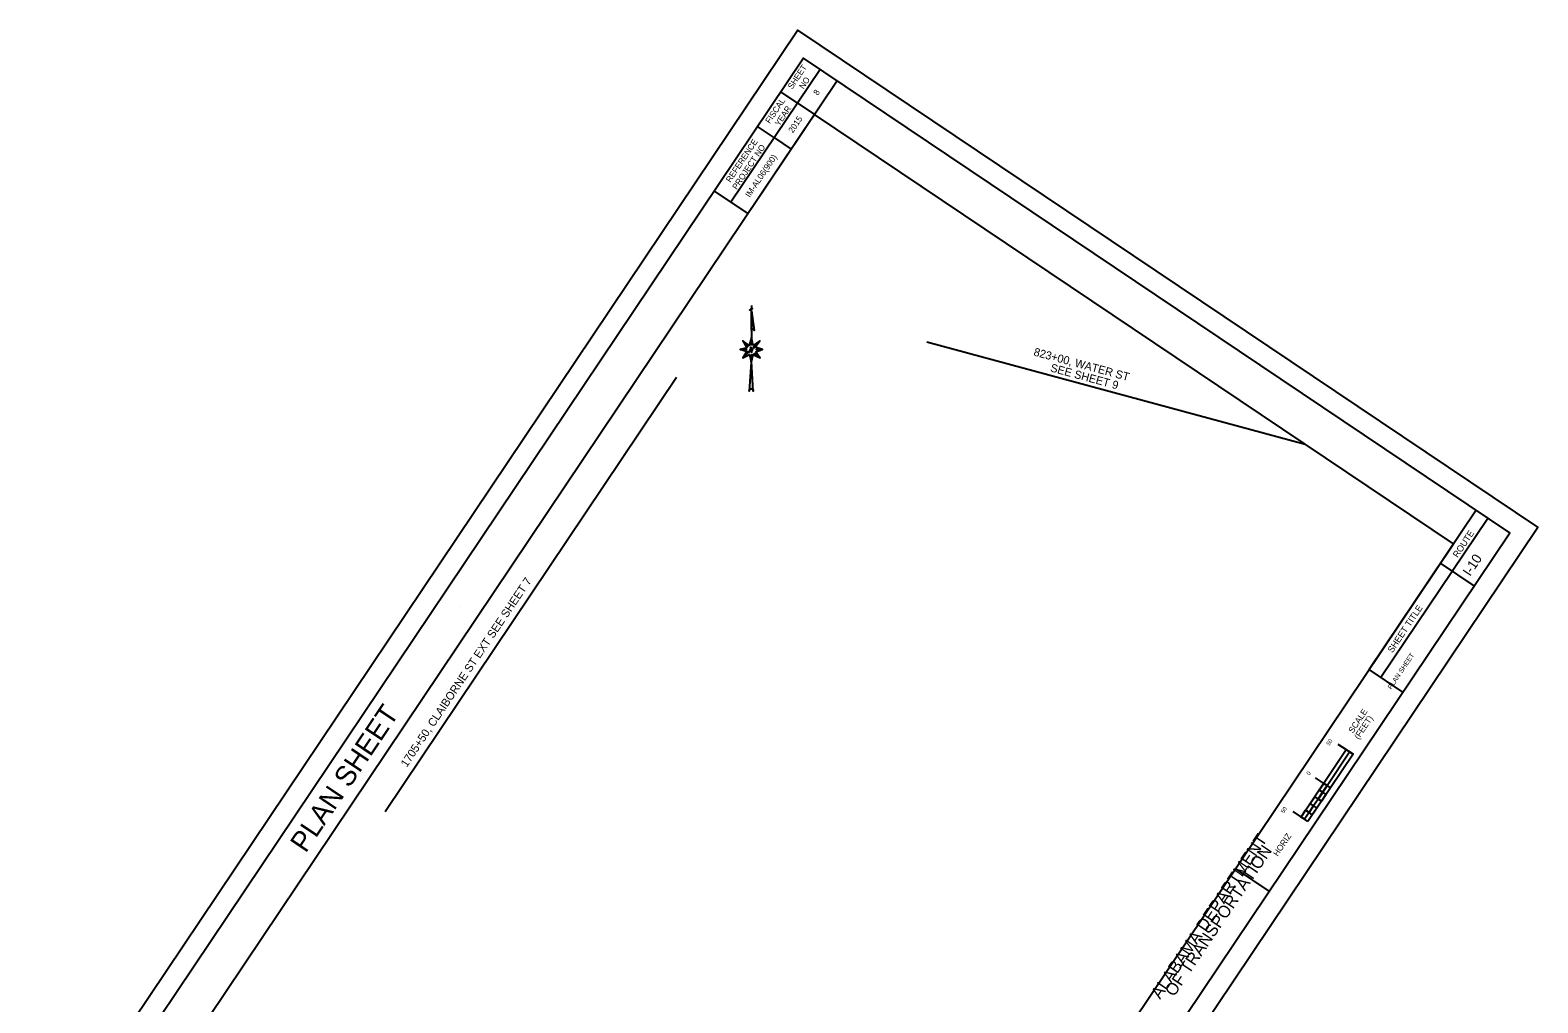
# Model space of a CAD drawing. Extents: x 1797784 to 1799645, y 248583 to 250607.
# Drawn here: x 1797784 to 1799645, y 249407 to 250607 of the extents above; entities that cross this region are included whole.
import ezdxf

# ---------------------------------------------------------------- set-up
doc = ezdxf.new("R2010")
doc.units = 0
for name, color, linetype in [('29', 7, 'Continuous'), ('ANNO-SHT', 7, 'Continuous'), ('ANNO-SYMB', 7, 'Continuous'), ('ANNO-TXT', 7, 'Continuous'), ('DRAINAGE', 7, 'Continuous'), ('Level 1', 7, 'Continuous'), ('Level 57', 7, 'Continuous'), ('Level 6', 7, 'Continuous'), ('Level 62', 7, 'Continuous'), ('SHT-BDR', 7, 'Continuous'), ('SHT-BNDRY', 7, 'Continuous')]:
    doc.layers.add(name, color=color, linetype=linetype)

# ---------------------------------------------------------------- blocks, each defined once
blk = doc.blocks.new('SC47208')
at = {"layer": 'Level 1'}
blk.add_line((0, 0), (0, 0), dxfattribs=at)

msp = doc.modelspace()

# ---------------------------------------------------------------- linework, layer by layer
at = {"layer": '29'}
msp.add_line((1798222.5, 249643.4), (1798582.1, 250179), dxfattribs=at)
msp.add_lwpolyline([(1798891.2, 250222.5), (1799358.1, 250096.4)], dxfattribs=at)
at = {"layer": 'ANNO-SYMB'}
for p, q in [((1799408.9, 249719.5), (1799353.1, 249636.4)), ((1799417.2, 249713.9), (1799361.4, 249630.9)), ((1799417.2, 249713.9), (1799398.9, 249726.1)), ((1799417.2, 249713.9), (1799413, 249716.7)), ((1799417.2, 249713.9), (1799413, 249716.7)), ((1799417.2, 249713.9), (1799413, 249716.7)), ((1799389.3, 249672.4), (1799371, 249684.6)), ((1799389.3, 249672.4), (1799371, 249684.6)), ((1799389.3, 249672.4), (1799371, 249684.6)), ((1799385.2, 249675.2), (1799374, 249658.6)), ((1799385.2, 249675.2), (1799381, 249677.9)), ((1799385.2, 249675.2), (1799381, 249677.9)), ((1799385.2, 249675.2), (1799381, 249677.9)), ((1799361.4, 249630.9), (1799343.2, 249643.1)), ((1799362.9, 249641.9), (1799358.7, 249644.7)), ((1799362.9, 249641.9), (1799358.7, 249644.7))]:
    msp.add_line(p, q, dxfattribs=at)
for points in [[(1799385.2, 249675.2), (1799413, 249716.7), (1799417.2, 249713.9), (1799389.3, 249672.4)], [(1799375.4, 249669.6), (1799381, 249677.9), (1799385.2, 249675.2), (1799379.6, 249666.9)], [(1799364.3, 249653), (1799369.9, 249661.3), (1799374, 249658.6), (1799368.4, 249650.3)], [(1799374, 249658.6), (1799379.6, 249666.9), (1799383.7, 249664.1), (1799378.2, 249655.8)], [(1799353.1, 249636.4), (1799358.7, 249644.7), (1799362.9, 249641.9), (1799357.3, 249633.6)], [(1799362.9, 249641.9), (1799368.4, 249650.3), (1799372.6, 249647.5), (1799367, 249639.2)]]:
    msp.add_lwpolyline(points, close=True, dxfattribs=at)
at = {"layer": 'ANNO-TXT'}
for p, q in [((1799539.4, 249939.7), (1799583.5, 250005.3)), ((1799451.6, 249808.8), (1799539.4, 249939.7))]:
    msp.add_line(p, q, dxfattribs=at)
at = {"layer": 'Level 57'}
msp.add_line((1798674.7, 250267.3), (1798674.6, 250264.8), dxfattribs=at)
for points in [[(1798675.8, 250263.7), (1798675.7, 250263.7), (1798675.8, 250263.5), (1798675.9, 250263.7), (1798675.8, 250263.9), (1798675.6, 250263.8), (1798675.3, 250263.7), (1798675.2, 250263.6), (1798675, 250263.2), (1798674.9, 250262.8), (1798674.7, 250262.2), (1798674.6, 250262.1), (1798674.5, 250261.7), (1798674.5, 250262.3), (1798674.4, 250263.2), (1798674.2, 250263.8), (1798674.3, 250263.2), (1798674.5, 250261.7), (1798674.4, 250263.2), (1798674.2, 250263.8), (1798674.1, 250263.3), (1798673.7, 250262.2), (1798673.4, 250261.7), (1798673.2, 250261.6), (1798672.9, 250261.6), (1798672.8, 250261.7), (1798672.8, 250261.9), (1798672.9, 250262), (1798673, 250261.9), (1798673, 250261.8)], [(1798674.6, 250260.8), (1798678.2, 250236.6), (1798678.1, 250237.4), (1798677.9, 250237.7), (1798677.5, 250238), (1798677, 250238.3), (1798676.7, 250238.3), (1798676.3, 250238.3), (1798675.9, 250238.4), (1798675.6, 250238.2), (1798675.3, 250238.1), (1798674.9, 250237.8), (1798674.8, 250237.6), (1798674.6, 250237.3), (1798674.6, 250237.1), (1798674.6, 250260.6), (1798674.7, 250227.7)], [(1798674.6, 250227.7), (1798674.5, 250218.8), (1798674.6, 250227.8), (1798671.9, 250218.2), (1798664.1, 250223.7), (1798670.2, 250217), (1798664.1, 250223.7), (1798669, 250215.2), (1798661, 250213.2), (1798668.6, 250213), (1798661.1, 250213.4), (1798668.9, 250210.6), (1798664.3, 250202.7), (1798670, 250208.5), (1798664.3, 250202.7), (1798672.2, 250207.1), (1798674.5, 250198.2), (1798674.4, 250206.5), (1798674.5, 250198), (1798676.5, 250207), (1798685.4, 250202.8), (1798676.4, 250207), (1798674.5, 250197.7), (1798672.1, 250161.7), (1798672.3, 250162.9), (1798672.7, 250163.7), (1798673.1, 250164.2), (1798673.8, 250164.6), (1798674.3, 250164.7), (1798674.9, 250164.7), (1798675.4, 250164.5), (1798676, 250164.2), (1798676.4, 250163.7), (1798676.7, 250163.1), (1798676.9, 250162.6), (1798677, 250161.7), (1798674.6, 250198.2), (1798676.4, 250207.1), (1798685.3, 250202.8), (1798678.5, 250208.1), (1798685.2, 250203), (1798680, 250210.1), (1798688, 250213.1), (1798680.4, 250213), (1798688.2, 250213.1), (1798679.4, 250215.9), (1798684.9, 250223.7), (1798678.5, 250217.4), (1798684.9, 250223.7), (1798677, 250218.2), (1798674.7, 250227.6)], [(1798678.5, 250215.7), (1798678.3, 250215.5), (1798678.6, 250215.2), (1798678.7, 250215.6), (1798678.6, 250215.9), (1798678.5, 250216.1), (1798677.9, 250216), (1798677.3, 250215.7), (1798676.3, 250214.5), (1798676.1, 250214), (1798675.8, 250212.8), (1798675.3, 250211.6), (1798674.8, 250210.7), (1798674.7, 250209.3), (1798674.7, 250211.1), (1798674.5, 250213.3), (1798674.4, 250214.5), (1798673.9, 250215.9), (1798673.9, 250214.2), (1798674.1, 250212), (1798674.4, 250210.5), (1798674.7, 250209.4), (1798674.6, 250211.4), (1798674.4, 250214.5), (1798673.9, 250216), (1798673.6, 250214.5), (1798672.9, 250212.9), (1798672.6, 250212.2), (1798672.4, 250211.4), (1798672, 250210.6), (1798671.7, 250210.1), (1798671.4, 250209.5), (1798670.6, 250209.2), (1798670, 250209.3), (1798669.7, 250209.6), (1798669.7, 250210.3), (1798670.1, 250210.6), (1798670.4, 250210.2), (1798670.1, 250210)]]:
    msp.add_lwpolyline(points, dxfattribs=at)
at = {"layer": 'Level 6'}
for p, q in [((1798759.4, 250558.6), (1798649.4, 250394.8)), ((1798780.4, 250544.6), (1798673.8, 250385.8)), ((1798731.2, 250517.3), (1798711, 250530.9)), ((1798731.2, 250517.3), (1798752.5, 250503)), ((1798703.1, 250474.2), (1798682.3, 250488.2)), ((1798703.1, 250474.2), (1798723.8, 250460.3)), ((1798628.9, 250408.6), (1798670.4, 250380.8)), ((1799569.1, 250015), (1799437.2, 249818.5))]:
    msp.add_line(p, q, dxfattribs=at)
at = {"layer": 'Level 62'}
msp.add_lwpolyline([(1798697.7, 248582.5), (1799645.3, 249993.9), (1798732.1, 250607.1), (1797784.5, 249195.7)], close=True, dxfattribs=at)
at = {"layer": 'SHT-BDR'}
msp.add_lwpolyline([(1798705.1, 248728.1), (1799541.2, 249973.5), (1798752.5, 250503), (1797916.4, 249257.7)], close=True, dxfattribs=at)
at = {"layer": 'SHT-BNDRY'}
for p, q in [((1799566.6, 249921.5), (1799525, 249949.4)), ((1799478.7, 249790.6), (1799437.2, 249818.5)), ((1799313.7, 249544.9), (1799272.2, 249572.8))]:
    msp.add_line(p, q, dxfattribs=at)
msp.add_lwpolyline([(1798711.8, 248648.4), (1799610.7, 249987.1), (1798738.9, 250572.4), (1797840.1, 249233.7)], close=True, dxfattribs=at)

# ---------------------------------------------------------------- block references
at = {"layer": 'DRAINAGE', "xscale": 1.0000020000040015, "yscale": 1.0000020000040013, "rotation": -60.2945162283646}
msp.add_blockref('SC47208', (1798313.8, 249896.2), dxfattribs=at)
msp.add_blockref('SC47208', (1798313.8, 249896.2), dxfattribs=at)

# ---------------------------------------------------------------- texts
at = {"layer": 'ANNO-SHT'}
for s, height, rotation, p in [('8', 7.45, 56.1222, (1798756.6, 250526)), ('2015', 7.45, 56.1222, (1798725.8, 250479.5)), ('IM-AL06(900)', 7.449, 56.1222, (1798672.7, 250400.1)), ('823+00, WATER ST', 10, 344.8847, (1799022.3, 250205.9)), ('SEE SHEET 9', 10, 344.8847, (1799042.9, 250186.3)), ('  I-10  ', 12, 56.1222, (1799556.7, 249925.2)), ('1705+50, CLAIBORNE ST EXT SEE SHEET 7', 10, 56.1222, (1798249.3, 249697.1)), ('               PLAN SHEET               ', 6, 56.1222, (1799445.2, 249764.7)), ('               PLAN SHEET               ', 24.998, 56.1222, (1798046.9, 249475.4))]:
    msp.add_text(s, height=height, rotation=rotation, dxfattribs=at).set_placement(p)
at = {"layer": 'ANNO-SYMB'}
for s, height, p in [('SCALE', 7.5, (1799417.2, 249739.3)), ('(FEET)', 7.5, (1799424.3, 249731.6)), (' 50', 5, (1799386.9, 249722.6)), ('0', 5, (1799363.4, 249687.5)), ('0', 5, (1799363.4, 249687.5)), ('0', 5, (1799363.4, 249687.5)), (' 50', 5, (1799330.7, 249638.9)), ('HORIZ', 7.5, (1799324.3, 249587.3))]:
    msp.add_text(s, height=height, rotation=56.1794, dxfattribs=at).set_placement(p)
at = {"layer": 'ANNO-TXT'}
for s, height, rotation, p in [('ROUTE', 8, 56.1222, (1799546.4, 249955.7)), ('SHEET TITLE', 8, 56.1222, (1799465.9, 249838.3)), ('ALABAMA DEPARTMENT', 15, 56.1221, (1799179.1, 249410.8)), ('OF TRANSPORTATION', 15, 56.1221, (1799196.2, 249413.9))]:
    msp.add_text(s, height=height, rotation=rotation, dxfattribs=at).set_placement(p)
at = {"layer": 'Level 6'}
for s, p in [('SHEET', (1798725.1, 250533.7)), ('NO', (1798739.1, 250533.8)), ('FISCAL', (1798697.4, 250491.2)), ('YEAR', (1798709.2, 250488.1)), ('REFERENCE', (1798648.7, 250418.6)), ('PROJECT NO', (1798656.6, 250409.7))]:
    msp.add_text(s, height=7.44, rotation=56.1222, dxfattribs=at).set_placement(p)

doc.saveas('drawing.dxf')
